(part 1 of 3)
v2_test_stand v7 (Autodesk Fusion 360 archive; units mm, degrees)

design "v2_test_stand" references "DFR0523", "157mm_top_lid", "2020_extrusion_385", "150mm_glass_base"
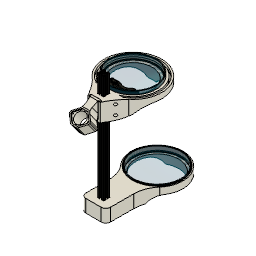
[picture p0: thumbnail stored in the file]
component_insert "Component Insert1"
component_insert "Component Insert2"
component_insert "Component Insert3"
sketch "Sketch1" plane through (0, 321.4508, 0) normal (0, 1, 0) x axis (-1, 0, 0)
  line L1 (-58.2856, 136.7071) -> (0, 97.9412)
  line L2 (0, 167.9412) -> (0, 97.9412)
  line L3 (58.2856, 136.7071) -> (0, 97.9412)
  circle C1 centre (0, 97.9412) radius 70
  circle C2 centre (0, 97.9412) radius 54.7046
  point P3 (0, 97.9412)
  point P4 (0, 97.9412)
  point P5 (-58.2856, 136.7071)
  point P2 (0, 97.9412)
  point P6 (0, 97.9412)
  point P7 (0, 167.9412)
  point P8 (0, 97.9412)
  point P9 (58.2856, 136.7071)
  concentric C1 C2
  coincident P3 P4
  coincident C1 P5
  coincident P2 P6
  vertical L2
  coincident C1 P7
  symmetric P4 L2 P8
  symmetric P5 L2 P9
extrude "Extrude1" new body sketch "Sketch1" profile of C1 C2 L1 L3 along normal blind 10
chamfer "Chamfer1" distance 10 distance 10
fillet "Fillet1" radius 2
sketch "Sketch2" plane through (0, 331.4508, 0) normal (0, 1, 0) x axis (-1, 0, 0)
position "Position1"
position "Position2"
sketch "Sketch3" plane through (0, 331.4508, 0) normal (0, 1, 0) x axis (-1, 0, 0)
  line L1 (58.2856, 136.7071) -> (54.5219, 134.2038)
  line L2 (-54.5219, 134.2038) -> (-58.2856, 136.7071)
  line L3 (-39.9313, 135.9208) -> (-53.1101, 133.8924)
  line L4 (53.1101, 133.8924) -> (39.9313, 135.9208)
  line L5 (0, 167.9412) -> (0, 152.6458)
  line L6 (-12.3083, 151.2431) -> (-14.4131, 166.4413)
  line L7 (12.3083, 151.2431) -> (14.4131, 166.4413)
  arc A1 centre (53.4143, 135.8691) radius 2 clockwise from (54.5219, 134.2038) to (53.1101, 133.8924)
  arc A2 centre (0, 97.9412) radius 70 clockwise from (-58.2856, 136.7071) to (58.2856, 136.7071)
  arc A3 centre (-53.4143, 135.8691) radius 2 clockwise from (-53.1101, 133.8924) to (-54.5219, 134.2038)
  arc A4 centre (-40.2356, 137.8975) radius 2 clockwise from (-38.8165, 136.4882) to (-39.9313, 135.9208)
  arc A5 centre (0, 97.9412) radius 54.7046 clockwise from (-38.8165, 136.4882) to (38.8165, 136.4882)
  arc A6 centre (40.2356, 137.8975) radius 2 clockwise from (39.9313, 135.9208) to (38.8165, 136.4882)
  point P17 (0, 152.6458)
  point P18 (0, 167.9412)
  point P19 (-14.4131, 166.4413)
  point P20 (-12.3083, 151.2431)
  point P21 (14.4131, 166.4413)
  point P22 (12.3083, 151.2431)
  midpoint A5 P17
  midpoint A2 P18
  coincident A2 P19
  coincident A5 P20
  symmetric L5 P19 P21
  symmetric L5 P20 P22
extrude "Extrude2" add sketch "Sketch3" profile of A2 A5 L5 L6 L7 along normal blind 12
fillet "Fillet2" radius 20
sketch "Sketch1" plane through (-21.1609, 0, 137.4854) normal (0.1521, 0, -0.9884) x axis (-0.9884, 0, -0.1521)
  line L1 (-0.9447, 331.4508) -> (-1.1938, 331.4508)
  line L2 (9.0966, 331.4508) -> (-0.9447, 331.4508)
  line L3 (10.2848, 331.4508) -> (9.0966, 331.4508)
  line L4 (23.6187, 331.4508) -> (10.2848, 331.4508)
  line L5 (24.9668, 331.4508) -> (23.6187, 331.4508)
  line L6 (28.3058, 331.4508) -> (24.9668, 331.4508)
  line L7 (-1.1938, 331.4508) -> (28.3058, 331.4508)
sketch "Sketch3" plane through (0, 331.4508, 0) normal (0, 1, 0) x axis (-1, 0, 0)
  curve K1 (21.1809, 143.8255) -> (3.7029, 151.2431)
  curve K2 (5.8078, 166.4413) -> (23.4449, 160.1729)
  line L1 (3.7029, 151.2431) -> (5.8078, 166.4413)
  line L2 (-20.9136, 151.2431) -> (-23.0185, 166.4413)
  line L3 (5.8078, 166.4413) -> (3.7029, 151.2431)
  curve K3 (-40.6556, 160.1729) -> (-23.0185, 166.4413)
  line L4 (-38.3916, 143.8255) -> (-40.6556, 160.1729)
  curve K4 (-20.9136, 151.2431) -> (-38.3916, 143.8255)
  line L5 (-23.0185, 166.4413) -> (-20.9136, 151.2431)
  line L6 (-40.6556, 160.1729) -> (-38.3916, 143.8255)
  line L7 (-63.1272, 134.2038) -> (-66.8909, 136.7071)
  line L8 (-48.5367, 135.9208) -> (-61.7154, 133.8924)
  line L9 (-8.6053, 167.9412) -> (-8.6053, 152.6458)
  line L10 (31.326, 135.9208) -> (44.5047, 133.8924)
  line L11 (49.6802, 136.7071) -> (45.9166, 134.2038)
  curve K5 (23.4449, 160.1729) -> (5.8078, 166.4413)
  arc A1 centre (-8.6053, 97.9412) radius 54.7046 clockwise from (-20.9136, 151.2431) to (3.7029, 151.2431)
  arc A2 centre (-8.6053, 97.9412) radius 70 clockwise from (-23.0185, 166.4413) to (5.8078, 166.4413)
  arc A3 centre (-8.6053, 97.9412) radius 70 clockwise from (-66.8909, 136.7071) to (-40.6556, 160.1729)
  arc A4 centre (-62.0197, 135.8691) radius 2 clockwise from (-61.7154, 133.8924) to (-63.1272, 134.2038)
  arc A5 centre (-48.8409, 137.8975) radius 2 clockwise from (-47.4218, 136.4882) to (-48.5367, 135.9208)
  arc A6 centre (-8.6053, 97.9412) radius 54.7046 clockwise from (-47.4218, 136.4882) to (-38.3916, 143.8255)
  arc A7 centre (-8.6053, 97.9412) radius 54.7046 clockwise from (21.1809, 143.8255) to (30.2111, 136.4882)
  arc A8 centre (31.6302, 137.8975) radius 2 clockwise from (31.326, 135.9208) to (30.2111, 136.4882)
  arc A9 centre (44.809, 135.8691) radius 2 clockwise from (45.9166, 134.2038) to (44.5047, 133.8924)
  arc A10 centre (-8.6053, 97.9412) radius 70 clockwise from (23.4449, 160.1729) to (49.6802, 136.7071)
  point P25 (-8.6053, 152.6458)
  point P26 (-8.6053, 167.9412)
  midpoint A1 P25
  midpoint A2 P26
work_plane "WorkPlane1" AlongDistance 0
sketch "Sketch4" plane through (0, 343.4508, 0) normal (0, 1, 0) x axis (-1, 0, 0)
  line L1 (-20.9136, 151.2431) -> (-23.0185, 166.4413)
  line L2 (5.8078, 166.4413) -> (3.7029, 151.2431)
  curve K1 (21.1809, 143.8255) -> (3.7029, 151.2431)
  line L3 (23.4449, 160.1729) -> (21.1809, 143.8255)
  curve K2 (5.8078, 166.4413) -> (23.4449, 160.1729)
  line L4 (3.7029, 151.2431) -> (5.8078, 166.4413)
  line L5 (21.1809, 143.8255) -> (23.4449, 160.1729)
  line L6 (44.5047, 133.8924) -> (31.326, 135.9208)
  line L7 (49.6802, 136.7071) -> (45.9166, 134.2038)
  line L8 (-8.6053, 167.9412) -> (-8.6053, 152.6458)
  line L9 (45.3089, 103.8063) -> (40.8089, 103.8063)
  line L10 (45.3089, 96.3993) -> (45.3089, 103.8063)
  line L11 (40.8089, 96.3993) -> (45.3089, 96.3993)
  line L12 (40.8089, 103.8063) -> (40.8089, 96.3993)
  line L13 (45.3089, 96.3993) -> (40.8089, 103.8063)
  line L14 (40.8089, 96.3993) -> (45.3089, 103.8063)
  curve K3 (4.9489, 162.359) -> (21.5349, 156.4642)
  curve K4 (25.1345, 149.9158) -> (5.3365, 158.318)
  arc A1 centre (-8.6053, 97.9412) radius 54.7046 clockwise from (-20.9136, 151.2431) to (3.7029, 151.2431)
  arc A2 centre (-8.6053, 97.9412) radius 70 clockwise from (-23.0185, 166.4413) to (5.8078, 166.4413)
  arc A3 centre (-8.6053, 97.9412) radius 54.7046 clockwise from (21.1809, 143.8255) to (30.2111, 136.4882)
  arc A4 centre (31.6302, 137.8975) radius 2 clockwise from (31.326, 135.9208) to (30.2111, 136.4882)
  arc A5 centre (44.809, 135.8691) radius 2 clockwise from (45.9166, 134.2038) to (44.5047, 133.8924)
  arc A6 centre (-8.6053, 97.9412) radius 70 clockwise from (23.4449, 160.1729) to (49.6802, 136.7071)
  arc A7 centre (43.0589, 97.8248) radius 2.6636 clockwise from (45.3089, 96.3993) to (40.8089, 96.3993)
  arc A8 centre (-8.6053, 97.9412) radius 65.8284 clockwise from (21.5349, 156.4642) to (46.2067, 134.3968)
  arc A9 centre (-8.6053, 97.9412) radius 65.8284 clockwise from (-22.1595, 162.359) to (4.9489, 162.359)
  arc A10 centre (-8.6053, 97.9412) radius 61.9656 clockwise from (25.1345, 149.9158) to (35.3633, 141.6046)
  arc A11 centre (-8.6053, 97.9412) radius 61.9656 clockwise from (-22.5473, 158.318) to (5.3365, 158.318)
  arc A12 centre (-11.8522, 103.1847) radius 60.872 clockwise from (35.3633, 141.6046) to (40.3255, 134.5357)
  point P21 (-8.6053, 152.6458)
  point P22 (-8.6053, 167.9412)
  point P27 (43.0589, 100.1028)
  point P41 (40.3255, 134.5357)
  midpoint A1 P21
  midpoint A2 P22
  horizontal L9
  perpendicular L9 L10
  parallel L9 L11
  parallel L10 L12
  coincident L13 P27
  coincident L14 P27
  tangent A3 A12
  coincident L6 P41
  dimension "d13" distance L10 L12 = 4.5
  dimension "d20" = 7.261
sketch "Sketch5" plane through (0, 0, 0) normal (0, 1, 0) x axis (1, 0, 0)
  line L1 (-8.9851, -14.6519) -> (-13.4777, -14.6519)
  line L2 (-8.9851, -23.8412) -> (-8.9851, -14.6519)
  line L3 (-13.4777, -23.8412) -> (-8.9851, -23.8412)
  line L4 (-13.4777, -14.6519) -> (-13.4777, -23.8412)
  line L5 (-8.9851, -23.8412) -> (-13.4777, -14.6519)
  line L6 (-13.4777, -23.8412) -> (-8.9851, -14.6519)
  arc A1 centre (-11.2314, -23.8412) radius 2.2463 clockwise from (-8.9851, -23.8412) to (-13.4777, -23.8412)
  point P6 (-11.2314, -19.2465)
  horizontal L1
  perpendicular L1 L2
  parallel L1 L3
  parallel L2 L4
  coincident L5 P6
  coincident L6 P6
  tangent L4 A1
emboss "Emboss1" sketch "Sketch4" Depth -7 Horizontal Distance 0 Vertical Distance 0 Rotation Angle 0
sketch "Sketch6" plane through (0, 343.4508, 0) normal (0, 1, 0) x axis (-1, 0, 0)
  line L1 (-20.9136, 151.2431) -> (-23.0185, 166.4413)
  line L2 (4.729, 158.6515) -> (3.7029, 151.2431)
  line L3 (5.2589, 162.4778) -> (4.729, 158.6515)
  line L4 (5.8078, 166.4413) -> (5.2589, 162.4778)
  line L5 (-8.6053, 152.6458) -> (-8.6053, 167.9412)
  line L6 (5.2589, 162.4778) -> (-1.0961, 163.3579)
  line L7 (4.729, 158.6515) -> (-1.626, 159.5316)
  arc A1 centre (-8.6053, 97.9412) radius 54.7046 clockwise from (-20.9136, 151.2431) to (3.7029, 151.2431)
  arc A2 centre (-8.6053, 97.9412) radius 70 clockwise from (-23.0185, 166.4413) to (5.8078, 166.4413)
  arc A3 centre (-0.0493, 167.9412) radius 8.5561 clockwise from (-1.626, 159.5316) to (-8.6053, 167.9412)
  arc A4 centre (2.5633, 168.6935) radius 5.8374 clockwise from (1.0129, 163.0658) to (-3.1943, 167.7317)
  point P9 (-8.6053, 167.9412)
  point P10 (-8.6053, 152.6458)
  point P11 (-1.626, 159.5316)
  point P13 (-1.626, 159.5316)
  point P15 (-3.1943, 167.7317)
  point P14 (1.0129, 163.0658)
  point P19 (-1.626, 159.5316)
  point P6 (4.729, 158.6515)
  point P20 (4.729, 158.6515)
  midpoint A2 P9
  midpoint A1 P10
  tangent L5 A3
  coincident P11 P13
  tangent A3 A4
  coincident A2 P15
  coincident P14 L6
  coincident P13 P19
  coincident P6 P20
extrude "Extrude3" cut sketch "Sketch6" profile of L3 A2 A3 A4 L6 L7 against normal blind 7.876
fillet "Fillet3" radius 1
fillet "Fillet4" radius 4
chamfer "Chamfer2" distance 2.438 distance 6.339
fillet "Fillet5" radius 1
work_plane "WorkPlane1" RotateAngle 90
split "Split1"
mirror "Mirror1" mirrorStitchTolerance 0.1
fillet "Fillet6" radius 3
remove_body "RemoveBody1"
sketch "Sketch4" plane through (0, 343.4508, 0) normal (0, 1, 0) x axis (-1, 0, 0)
  line L1 (-10.9032, 158.9882) -> (-6.9794, 159.5316)
  line L2 (-9.8997, 151.7426) -> (-10.9032, 158.9882)
  line L3 (10.9032, 158.9882) -> (9.8997, 151.7426)
  line L4 (6.9794, 159.5316) -> (10.9032, 158.9882)
  line L5 (6.815, 158.5181) -> (9.7456, 158.1122)
  line L6 (-9.7456, 158.1122) -> (-6.815, 158.5181)
  line L7 (-9.0287, 152.9361) -> (-9.7456, 158.1122)
  line L8 (9.7456, 158.1122) -> (9.0287, 152.9361)
  arc A1 centre (0, 160.1735) radius 3 clockwise from (-2.2212, 162.19) to (2.2212, 162.19)
  arc A2 centre (-8.5561, 167.9412) radius 8.5561 clockwise from (-2.2212, 162.19) to (-6.9794, 159.5316)
  arc A3 centre (0, 97.9412) radius 54.7046 clockwise from (-9.8997, 151.7426) to (9.8997, 151.7426)
  arc A4 centre (8.5561, 167.9412) radius 8.5561 clockwise from (6.9794, 159.5316) to (2.2212, 162.19)
  arc A5 centre (8.5561, 167.9412) radius 9.5826 clockwise from (6.815, 158.5181) to (1.4612, 161.5)
  arc A6 centre (0, 160.1735) radius 1.9735 clockwise from (-1.4612, 161.5) to (1.4612, 161.5)
  arc A7 centre (-8.5561, 167.9412) radius 9.5826 clockwise from (-1.4612, 161.5) to (-6.815, 158.5181)
  arc A8 centre (0, 97.9412) radius 55.7311 clockwise from (-9.0287, 152.9361) to (9.0287, 152.9361)
  dimension "d41" = -1.0265
extrude "Extrude4" cut sketch "Sketch4" profile of L8 L7 A8 A7 L6 A6 A5 L5 against normal blind 1.4
sketch "Sketch5" plane through (0, 319.8908, 0) normal (0, -1, 0) x axis (1, 0, 0)
  line L1 (11.3947, 201.5) -> (11.3947, 195.7)
  line L2 (4.5947, 202.5) -> (10.3947, 202.5)
  line L3 (4.5947, 200.7) -> (4.5947, 202.5)
  line L4 (6.3447, 200.7) -> (4.5947, 200.7)
  line L5 (6.8447, 199.1071) -> (6.8447, 200.2)
  line L6 (4.4911, 196.5464) -> (6.6982, 198.7536)
  line L7 (-1.3482, 196.4) -> (4.1375, 196.4)
  line L8 (-3.9089, 198.7536) -> (-1.7018, 196.5464)
  line L9 (-4.0553, 200.2) -> (-4.0553, 199.1071)
  line L10 (-1.8053, 200.7) -> (-3.5553, 200.7)
  line L11 (-1.8053, 202.5) -> (-1.8053, 200.7)
  line L12 (-7.6053, 202.5) -> (-1.8053, 202.5)
  line L13 (-8.6053, 195.7) -> (-8.6053, 201.5)
  line L14 (-6.8053, 195.7) -> (-8.6053, 195.7)
  line L15 (-6.8053, 197.45) -> (-6.8053, 195.7)
  line L16 (-5.2125, 197.95) -> (-6.3053, 197.95)
  line L17 (-2.6518, 195.5964) -> (-4.8589, 197.8036)
  line L18 (-2.5053, 189.7571) -> (-2.5053, 195.2429)
  line L19 (-4.8589, 187.1964) -> (-2.6518, 189.4036)
  line L20 (-6.3053, 187.05) -> (-5.2125, 187.05)
  line L21 (-6.8053, 189.3) -> (-6.8053, 187.55)
  line L22 (-8.6053, 189.3) -> (-6.8053, 189.3)
  line L23 (-8.6053, 183.5) -> (-8.6053, 189.3)
  line L24 (-1.8053, 182.5) -> (-7.6053, 182.5)
  line L25 (-1.8053, 184.3) -> (-1.8053, 182.5)
  line L26 (-3.5553, 184.3) -> (-1.8053, 184.3)
  line L27 (-4.0553, 185.8929) -> (-4.0553, 184.8)
  line L28 (-1.7018, 188.4536) -> (-3.9089, 186.2464)
  line L29 (4.1375, 188.6) -> (-1.3482, 188.6)
  line L30 (6.6982, 186.2464) -> (4.4911, 188.4536)
  line L31 (6.8447, 184.8) -> (6.8447, 185.8929)
  line L32 (4.5947, 184.3) -> (6.3447, 184.3)
  line L33 (4.5947, 182.5) -> (4.5947, 184.3)
  line L34 (10.3947, 182.5) -> (4.5947, 182.5)
  line L35 (11.3947, 189.3) -> (11.3947, 183.5)
  line L36 (9.5947, 189.3) -> (11.3947, 189.3)
  line L37 (9.5947, 187.55) -> (9.5947, 189.3)
  line L38 (8.0018, 187.05) -> (9.0947, 187.05)
  line L39 (5.4411, 189.4036) -> (7.6482, 187.1964)
  line L40 (5.2947, 195.2429) -> (5.2947, 189.7571)
  line L41 (7.6482, 197.8036) -> (5.4411, 195.5964)
  line L42 (9.0947, 197.95) -> (8.0018, 197.95)
  line L43 (9.5947, 195.7) -> (9.5947, 197.45)
  line L44 (11.3947, 195.7) -> (9.5947, 195.7)
  line L45 (21.0401, 215.2474) -> (-18.2508, 215.2474)
  line L46 (21.0401, 169.7526) -> (21.0401, 215.2474)
  line L47 (-18.2508, 169.7526) -> (21.0401, 169.7526)
  line L48 (-18.2508, 215.2474) -> (-18.2508, 169.7526)
  line L49 (21.0401, 169.7526) -> (-18.2508, 215.2474)
  line L50 (-18.2508, 169.7526) -> (21.0401, 215.2474)
  arc A1 centre (10.3947, 201.5) radius 1 clockwise from (10.3947, 202.5) to (11.3947, 201.5)
  arc A2 centre (6.3447, 200.2) radius 0.5 clockwise from (6.3447, 200.7) to (6.8447, 200.2)
  arc A3 centre (6.3447, 199.1071) radius 0.5 clockwise from (6.8447, 199.1071) to (6.6982, 198.7536)
  arc A4 centre (4.1375, 196.9) radius 0.5 clockwise from (4.4911, 196.5464) to (4.1375, 196.4)
  arc A5 centre (-1.3482, 196.9) radius 0.5 clockwise from (-1.3482, 196.4) to (-1.7018, 196.5464)
  arc A6 centre (-3.5553, 199.1071) radius 0.5 clockwise from (-3.9089, 198.7536) to (-4.0553, 199.1071)
  arc A7 centre (-3.5553, 200.2) radius 0.5 clockwise from (-4.0553, 200.2) to (-3.5553, 200.7)
  arc A8 centre (-7.6053, 201.5) radius 1 clockwise from (-8.6053, 201.5) to (-7.6053, 202.5)
  arc A9 centre (-6.3053, 197.45) radius 0.5 clockwise from (-6.8053, 197.45) to (-6.3053, 197.95)
  arc A10 centre (-5.2125, 197.45) radius 0.5 clockwise from (-5.2125, 197.95) to (-4.8589, 197.8036)
  arc A11 centre (-3.0053, 195.2429) radius 0.5 clockwise from (-2.6518, 195.5964) to (-2.5053, 195.2429)
  arc A12 centre (-3.0053, 189.7571) radius 0.5 clockwise from (-2.5053, 189.7571) to (-2.6518, 189.4036)
  arc A13 centre (-5.2125, 187.55) radius 0.5 clockwise from (-4.8589, 187.1964) to (-5.2125, 187.05)
  arc A14 centre (-6.3053, 187.55) radius 0.5 clockwise from (-6.3053, 187.05) to (-6.8053, 187.55)
  arc A15 centre (-7.6053, 183.5) radius 1 clockwise from (-7.6053, 182.5) to (-8.6053, 183.5)
  arc A16 centre (-3.5553, 184.8) radius 0.5 clockwise from (-3.5553, 184.3) to (-4.0553, 184.8)
  arc A17 centre (-3.5553, 185.8929) radius 0.5 clockwise from (-4.0553, 185.8929) to (-3.9089, 186.2464)
  arc A18 centre (-1.3482, 188.1) radius 0.5 clockwise from (-1.7018, 188.4536) to (-1.3482, 188.6)
  arc A19 centre (4.1375, 188.1) radius 0.5 clockwise from (4.1375, 188.6) to (4.4911, 188.4536)
  arc A20 centre (6.3447, 185.8929) radius 0.5 clockwise from (6.6982, 186.2464) to (6.8447, 185.8929)
  arc A21 centre (6.3447, 184.8) radius 0.5 clockwise from (6.8447, 184.8) to (6.3447, 184.3)
  arc A22 centre (10.3947, 183.5) radius 1 clockwise from (11.3947, 183.5) to (10.3947, 182.5)
  arc A23 centre (9.0947, 187.55) radius 0.5 clockwise from (9.5947, 187.55) to (9.0947, 187.05)
  arc A24 centre (8.0018, 187.55) radius 0.5 clockwise from (8.0018, 187.05) to (7.6482, 187.1964)
  arc A25 centre (5.7947, 189.7571) radius 0.5 clockwise from (5.4411, 189.4036) to (5.2947, 189.7571)
  arc A26 centre (5.7947, 195.2429) radius 0.5 clockwise from (5.2947, 195.2429) to (5.4411, 195.5964)
  arc A27 centre (8.0018, 197.45) radius 0.5 clockwise from (7.6482, 197.8036) to (8.0018, 197.95)
  arc A28 centre (9.0947, 197.45) radius 0.5 clockwise from (9.0947, 197.95) to (9.5947, 197.45)
  circle C1 centre (1.3947, 192.5) radius 2.5
  circle C2 centre (0, 97.9412) radius 72.5
  circle C3 centre (0, 97.9412) radius 72.7
  circle C4 centre (0, 97.9412) radius 92.5
  point P110 (1.3947, 192.5)
  point P102 (1.3947, 192.5)
  horizontal L45
  perpendicular L45 L46
  parallel L45 L47
  parallel L46 L48
  coincident L49 P110
  coincident L50 P110
  coincident P102 P110
  dimension "d44" = 0.2
  dimension "d45" = 20
extrude "Extrude5" new body sketch "Sketch5" profile of L1 A1 L2 L3 L4 A2 L5 A3 L6 A4 L7 A5 L8 A6 L9 A7 L10 L11 L12 A8 L13 L14 L15 A9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 along normal blind 10
sketch "Sketch6" plane through (0, 319.8908, 0) normal (0, 1, 0) x axis (-1, 0, 0)
  line L1 (-9.5947, 195.7) -> (-9.5947, 197.45)
  line L2 (-11.3947, 195.7) -> (-9.5947, 195.7)
  line L3 (-11.3947, 201.5) -> (-11.3947, 195.7)
  line L4 (-4.5947, 202.5) -> (-10.3947, 202.5)
  line L5 (-4.5947, 200.7) -> (-4.5947, 202.5)
  line L6 (-6.3447, 200.7) -> (-4.5947, 200.7)
  line L7 (-6.8447, 199.1071) -> (-6.8447, 200.2)
  line L8 (-4.4911, 196.5464) -> (-6.6982, 198.7536)
  line L9 (1.3482, 196.4) -> (-4.1375, 196.4)
  line L10 (3.9089, 198.7536) -> (1.7018, 196.5464)
  line L11 (4.0553, 200.2) -> (4.0553, 199.1071)
  line L12 (1.8053, 200.7) -> (3.5553, 200.7)
  line L13 (1.8053, 202.5) -> (1.8053, 200.7)
  line L14 (7.6053, 202.5) -> (1.8053, 202.5)
  line L15 (8.6053, 195.7) -> (8.6053, 201.5)
  line L16 (6.8053, 195.7) -> (8.6053, 195.7)
  line L17 (6.8053, 197.45) -> (6.8053, 195.7)
  line L18 (5.2125, 197.95) -> (6.3053, 197.95)
  line L19 (2.6518, 195.5964) -> (4.8589, 197.8036)
  line L20 (2.5053, 189.7571) -> (2.5053, 195.2429)
  line L21 (4.8589, 187.1964) -> (2.6518, 189.4036)
  line L22 (6.3053, 187.05) -> (5.2125, 187.05)
  line L23 (6.8053, 189.3) -> (6.8053, 187.55)
  line L24 (8.6053, 189.3) -> (6.8053, 189.3)
  line L25 (8.6053, 183.5) -> (8.6053, 189.3)
  line L26 (1.8053, 182.5) -> (7.6053, 182.5)
  line L27 (1.8053, 184.3) -> (1.8053, 182.5)
  line L28 (3.5553, 184.3) -> (1.8053, 184.3)
  line L29 (4.0553, 185.8929) -> (4.0553, 184.8)
  line L30 (1.7018, 188.4536) -> (3.9089, 186.2464)
  line L31 (-4.1375, 188.6) -> (1.3482, 188.6)
  line L32 (-6.6982, 186.2464) -> (-4.4911, 188.4536)
  line L33 (-6.8447, 184.8) -> (-6.8447, 185.8929)
  line L34 (-4.5947, 184.3) -> (-6.3447, 184.3)
  line L35 (-4.5947, 182.5) -> (-4.5947, 184.3)
  line L36 (-10.3947, 182.5) -> (-4.5947, 182.5)
  line L37 (-11.3947, 189.3) -> (-11.3947, 183.5)
  line L38 (-9.5947, 189.3) -> (-11.3947, 189.3)
  line L39 (-9.5947, 187.55) -> (-9.5947, 189.3)
  line L40 (-8.0018, 187.05) -> (-9.0947, 187.05)
  line L41 (-5.4411, 189.4036) -> (-7.6482, 187.1964)
  line L42 (-5.2947, 195.2429) -> (-5.2947, 189.7571)
  line L43 (-7.6482, 197.8036) -> (-5.4411, 195.5964)
  line L44 (-9.0947, 197.95) -> (-8.0018, 197.95)
  line L45 (18.2508, 215.2474) -> (18.2508, 188.6228)
  line L46 (-21.0401, 215.2474) -> (18.2508, 215.2474)
  line L47 (-21.0401, 188.0165) -> (-21.0401, 215.2474)
  circle C1 centre (0, 97.9412) radius 74.5
  circle C2 centre (0, 97.9412) radius 74.7
  arc A1 centre (-10.3947, 201.5) radius 1 clockwise from (-11.3947, 201.5) to (-10.3947, 202.5)
  arc A2 centre (-6.3447, 200.2) radius 0.5 clockwise from (-6.8447, 200.2) to (-6.3447, 200.7)
  arc A3 centre (-6.3447, 199.1071) radius 0.5 clockwise from (-6.6982, 198.7536) to (-6.8447, 199.1071)
  arc A4 centre (-4.1375, 196.9) radius 0.5 clockwise from (-4.1375, 196.4) to (-4.4911, 196.5464)
  arc A5 centre (1.3482, 196.9) radius 0.5 clockwise from (1.7018, 196.5464) to (1.3482, 196.4)
  arc A6 centre (3.5553, 199.1071) radius 0.5 clockwise from (4.0553, 199.1071) to (3.9089, 198.7536)
  arc A7 centre (3.5553, 200.2) radius 0.5 clockwise from (3.5553, 200.7) to (4.0553, 200.2)
  arc A8 centre (7.6053, 201.5) radius 1 clockwise from (7.6053, 202.5) to (8.6053, 201.5)
  arc A9 centre (6.3053, 197.45) radius 0.5 clockwise from (6.3053, 197.95) to (6.8053, 197.45)
  arc A10 centre (5.2125, 197.45) radius 0.5 clockwise from (4.8589, 197.8036) to (5.2125, 197.95)
  arc A11 centre (3.0053, 195.2429) radius 0.5 clockwise from (2.5053, 195.2429) to (2.6518, 195.5964)
  arc A12 centre (3.0053, 189.7571) radius 0.5 clockwise from (2.6518, 189.4036) to (2.5053, 189.7571)
  arc A13 centre (5.2125, 187.55) radius 0.5 clockwise from (5.2125, 187.05) to (4.8589, 187.1964)
  arc A14 centre (6.3053, 187.55) radius 0.5 clockwise from (6.8053, 187.55) to (6.3053, 187.05)
  arc A15 centre (7.6053, 183.5) radius 1 clockwise from (8.6053, 183.5) to (7.6053, 182.5)
  arc A16 centre (3.5553, 184.8) radius 0.5 clockwise from (4.0553, 184.8) to (3.5553, 184.3)
  arc A17 centre (3.5553, 185.8929) radius 0.5 clockwise from (3.9089, 186.2464) to (4.0553, 185.8929)
  arc A18 centre (1.3482, 188.1) radius 0.5 clockwise from (1.3482, 188.6) to (1.7018, 188.4536)
  arc A19 centre (-4.1375, 188.1) radius 0.5 clockwise from (-4.4911, 188.4536) to (-4.1375, 188.6)
  arc A20 centre (-6.3447, 185.8929) radius 0.5 clockwise from (-6.8447, 185.8929) to (-6.6982, 186.2464)
  arc A21 centre (-6.3447, 184.8) radius 0.5 clockwise from (-6.3447, 184.3) to (-6.8447, 184.8)
  arc A22 centre (-10.3947, 183.5) radius 1 clockwise from (-10.3947, 182.5) to (-11.3947, 183.5)
  arc A23 centre (-9.0947, 187.55) radius 0.5 clockwise from (-9.0947, 187.05) to (-9.5947, 187.55)
  arc A24 centre (-8.0018, 187.55) radius 0.5 clockwise from (-7.6482, 187.1964) to (-8.0018, 187.05)
  arc A25 centre (-5.7947, 189.7571) radius 0.5 clockwise from (-5.2947, 189.7571) to (-5.4411, 189.4036)
  arc A26 centre (-5.7947, 195.2429) radius 0.5 clockwise from (-5.4411, 195.5964) to (-5.2947, 195.2429)
  arc A27 centre (-8.0018, 197.45) radius 0.5 clockwise from (-8.0018, 197.95) to (-7.6482, 197.8036)
  arc A28 centre (-9.0947, 197.45) radius 0.5 clockwise from (-9.5947, 197.45) to (-9.0947, 197.95)
  arc A29 centre (0, 97.9412) radius 92.5 clockwise from (18.2508, 188.6228) to (-21.0401, 188.0165)
  dimension "d48" = 0.2
extrude "Extrude6" add sketch "Sketch6" profile of C2 L1 L2 L3 A1 L4 L5 L6 A2 L7 A3 L8 A4 L9 A5 L10 A6 L11 A7 L12 L13 L14 A8 L15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 along normal blind 7.53
chamfer "Chamfer3" distance 42 distance 10 distance 10 distance 42
sketch "Sketch7" plane through (0, 309.8908, 0) normal (0, -1, 0) x axis (1, 0, 0)
  circle C1 centre (0, 97.9412) radius 70
  circle C2 centre (0, 97.9412) radius 62
  concentric C1 C2
  dimension "d55" distance C1 C2 = 8
extrude "Extrude7" cut sketch "Sketch7" profile of C2 against normal blind 11.56
sketch "Sketch8" plane through (0, 309.8908, 0) normal (0, -1, 0) x axis (1, 0, 0)
  line L1 (9.5947, 197.45) -> (9.5947, 195.7)
  line L2 (8.0018, 197.95) -> (9.0947, 197.95)
  line L3 (5.4411, 195.5964) -> (7.6482, 197.8036)
  line L4 (5.2947, 189.7571) -> (5.2947, 195.2429)
  line L5 (7.6482, 187.1964) -> (5.4411, 189.4036)
  line L6 (9.0947, 187.05) -> (8.0018, 187.05)
  line L7 (9.5947, 189.3) -> (9.5947, 187.55)
  line L8 (11.3947, 189.3) -> (9.5947, 189.3)
  line L9 (11.3947, 183.5) -> (11.3947, 189.3)
  line L10 (4.5947, 182.5) -> (10.3947, 182.5)
  line L11 (4.5947, 184.3) -> (4.5947, 182.5)
  line L12 (6.3447, 184.3) -> (4.5947, 184.3)
  line L13 (6.8447, 185.8929) -> (6.8447, 184.8)
  line L14 (4.4911, 188.4536) -> (6.6982, 186.2464)
  line L15 (-1.3482, 188.6) -> (4.1375, 188.6)
  line L16 (-3.9089, 186.2464) -> (-1.7018, 188.4536)
  line L17 (-4.0553, 184.8) -> (-4.0553, 185.8929)
  line L18 (-1.8053, 184.3) -> (-3.5553, 184.3)
  line L19 (-1.8053, 182.5) -> (-1.8053, 184.3)
  line L20 (-7.6053, 182.5) -> (-1.8053, 182.5)
  line L21 (-8.6053, 189.3) -> (-8.6053, 183.5)
  line L22 (-6.8053, 189.3) -> (-8.6053, 189.3)
  line L23 (-6.8053, 187.55) -> (-6.8053, 189.3)
  line L24 (-5.2125, 187.05) -> (-6.3053, 187.05)
  line L25 (-2.6518, 189.4036) -> (-4.8589, 187.1964)
  line L26 (-2.5053, 195.2429) -> (-2.5053, 189.7571)
  line L27 (-4.8589, 197.8036) -> (-2.6518, 195.5964)
  line L28 (-6.3053, 197.95) -> (-5.2125, 197.95)
  line L29 (-6.8053, 195.7) -> (-6.8053, 197.45)
  line L30 (-8.6053, 195.7) -> (-6.8053, 195.7)
  line L31 (-8.6053, 201.5) -> (-8.6053, 195.7)
  line L32 (-1.8053, 202.5) -> (-7.6053, 202.5)
  line L33 (-1.8053, 200.7) -> (-1.8053, 202.5)
  line L34 (-3.5553, 200.7) -> (-1.8053, 200.7)
  line L35 (-4.0553, 199.1071) -> (-4.0553, 200.2)
  line L36 (-1.7018, 196.5464) -> (-3.9089, 198.7536)
  line L37 (4.1375, 196.4) -> (-1.3482, 196.4)
  line L38 (6.6982, 198.7536) -> (4.4911, 196.5464)
  line L39 (6.8447, 200.2) -> (6.8447, 199.1071)
  line L40 (4.5947, 200.7) -> (6.3447, 200.7)
  line L41 (4.5947, 202.5) -> (4.5947, 200.7)
  line L42 (10.3947, 202.5) -> (4.5947, 202.5)
  line L43 (11.3947, 195.7) -> (11.3947, 201.5)
  line L44 (9.5947, 195.7) -> (11.3947, 195.7)
  line L45 (-18.2508, 198.6228) -> (-18.2508, 215.2474)
  line L46 (-56.4687, 171.2046) -> (-18.2508, 198.6228)
  line L47 (21.0401, 198.0165) -> (58.7024, 169.4274)
  line L48 (21.0401, 215.2474) -> (21.0401, 198.0165)
  line L49 (-18.2508, 215.2474) -> (21.0401, 215.2474)
  line L50 (0, 5.4412) -> (0, 97.9412)
  line L51 (18.6886, 7.3488) -> (0, 97.9412)
  line L52 (-18.6886, 7.3488) -> (0, 97.9412)
  circle C1 centre (0, 97.9412) radius 62
  arc A1 centre (9.0947, 197.45) radius 0.5 clockwise from (9.0947, 197.95) to (9.5947, 197.45)
  arc A2 centre (8.0018, 197.45) radius 0.5 clockwise from (7.6482, 197.8036) to (8.0018, 197.95)
  arc A3 centre (5.7947, 195.2429) radius 0.5 clockwise from (5.2947, 195.2429) to (5.4411, 195.5964)
  arc A4 centre (5.7947, 189.7571) radius 0.5 clockwise from (5.4411, 189.4036) to (5.2947, 189.7571)
  arc A5 centre (8.0018, 187.55) radius 0.5 clockwise from (8.0018, 187.05) to (7.6482, 187.1964)
  arc A6 centre (9.0947, 187.55) radius 0.5 clockwise from (9.5947, 187.55) to (9.0947, 187.05)
  arc A7 centre (10.3947, 183.5) radius 1 clockwise from (11.3947, 183.5) to (10.3947, 182.5)
  arc A8 centre (6.3447, 184.8) radius 0.5 clockwise from (6.8447, 184.8) to (6.3447, 184.3)
  arc A9 centre (6.3447, 185.8929) radius 0.5 clockwise from (6.6982, 186.2464) to (6.8447, 185.8929)
  arc A10 centre (4.1375, 188.1) radius 0.5 clockwise from (4.1375, 188.6) to (4.4911, 188.4536)
  arc A11 centre (-1.3482, 188.1) radius 0.5 clockwise from (-1.7018, 188.4536) to (-1.3482, 188.6)
  arc A12 centre (-3.5553, 185.8929) radius 0.5 clockwise from (-4.0553, 185.8929) to (-3.9089, 186.2464)
  arc A13 centre (-3.5553, 184.8) radius 0.5 clockwise from (-3.5553, 184.3) to (-4.0553, 184.8)
  arc A14 centre (-7.6053, 183.5) radius 1 clockwise from (-7.6053, 182.5) to (-8.6053, 183.5)
  arc A15 centre (-6.3053, 187.55) radius 0.5 clockwise from (-6.3053, 187.05) to (-6.8053, 187.55)
  arc A16 centre (-5.2125, 187.55) radius 0.5 clockwise from (-4.8589, 187.1964) to (-5.2125, 187.05)
  arc A17 centre (-3.0053, 189.7571) radius 0.5 clockwise from (-2.5053, 189.7571) to (-2.6518, 189.4036)
  arc A18 centre (-3.0053, 195.2429) radius 0.5 clockwise from (-2.6518, 195.5964) to (-2.5053, 195.2429)
  arc A19 centre (-5.2125, 197.45) radius 0.5 clockwise from (-5.2125, 197.95) to (-4.8589, 197.8036)
  arc A20 centre (-6.3053, 197.45) radius 0.5 clockwise from (-6.8053, 197.45) to (-6.3053, 197.95)
  arc A21 centre (-7.6053, 201.5) radius 1 clockwise from (-8.6053, 201.5) to (-7.6053, 202.5)
  arc A22 centre (-3.5553, 200.2) radius 0.5 clockwise from (-4.0553, 200.2) to (-3.5553, 200.7)
  arc A23 centre (-3.5553, 199.1071) radius 0.5 clockwise from (-3.9089, 198.7536) to (-4.0553, 199.1071)
  arc A24 centre (-1.3482, 196.9) radius 0.5 clockwise from (-1.3482, 196.4) to (-1.7018, 196.5464)
  arc A25 centre (4.1375, 196.9) radius 0.5 clockwise from (4.4911, 196.5464) to (4.1375, 196.4)
  arc A26 centre (6.3447, 199.1071) radius 0.5 clockwise from (6.8447, 199.1071) to (6.6982, 198.7536)
  arc A27 centre (6.3447, 200.2) radius 0.5 clockwise from (6.3447, 200.7) to (6.8447, 200.2)
  arc A28 centre (10.3947, 201.5) radius 1 clockwise from (10.3947, 202.5) to (11.3947, 201.5)
  arc A29 centre (0, 97.9412) radius 92.5 clockwise from (58.7024, 169.4274) to (-56.4687, 171.2046)
  point P2 (0, 97.9412)
  point P109 (0, 97.9412)
  point P110 (0, 5.4412)
  point P111 (18.6886, 7.3488)
  point P112 (0, 97.9412)
  point P113 (-18.6886, 7.3488)
  coincident P2 P109
  coincident A29 P110
  vertical L50
  coincident A29 P111
  symmetric P109 L50 P112
  symmetric L50 P111 P113
extrude "Extrude8" add sketch "Sketch8" profile of C1 A29 L50 L51 L52 along normal blind 24
fillet "Fillet7" radius 70.291
sketch "Sketch9" plane through (0, 309.8908, 0) normal (0, -1, 0) x axis (1, 0, 0)
  line L1 (-58.3394, 76.9527) -> (-67.1363, 34.3097)
  line L2 (67.1364, 34.3097) -> (58.3394, 76.9527)
  line L3 (21.0401, 198.0165) -> (58.7024, 169.4274)
  line L4 (21.0401, 215.2474) -> (21.0401, 198.0165)
  line L5 (-18.2508, 215.2474) -> (21.0401, 215.2474)
  line L6 (-18.2508, 198.6228) -> (-18.2508, 215.2474)
  line L7 (-56.4687, 171.2046) -> (-18.2508, 198.6228)
  line L8 (9.5947, 197.45) -> (9.5947, 195.7)
  line L9 (8.0018, 197.95) -> (9.0947, 197.95)
  line L10 (5.4411, 195.5964) -> (7.6482, 197.8036)
  line L11 (5.2947, 189.7571) -> (5.2947, 195.2429)
  line L12 (7.6482, 187.1964) -> (5.4411, 189.4036)
  line L13 (9.0947, 187.05) -> (8.0018, 187.05)
  line L14 (9.5947, 189.3) -> (9.5947, 187.55)
  line L15 (11.3947, 189.3) -> (9.5947, 189.3)
  line L16 (11.3947, 183.5) -> (11.3947, 189.3)
  line L17 (4.5947, 182.5) -> (10.3947, 182.5)
  line L18 (4.5947, 184.3) -> (4.5947, 182.5)
  line L19 (6.3447, 184.3) -> (4.5947, 184.3)
  line L20 (6.8447, 185.8929) -> (6.8447, 184.8)
  line L21 (4.4911, 188.4536) -> (6.6982, 186.2464)
  line L22 (-1.3482, 188.6) -> (4.1375, 188.6)
  line L23 (-3.9089, 186.2464) -> (-1.7018, 188.4536)
  line L24 (-4.0553, 184.8) -> (-4.0553, 185.8929)
  line L25 (-1.8053, 184.3) -> (-3.5553, 184.3)
  line L26 (-1.8053, 182.5) -> (-1.8053, 184.3)
  line L27 (-7.6053, 182.5) -> (-1.8053, 182.5)
  line L28 (-8.6053, 189.3) -> (-8.6053, 183.5)
  line L29 (-6.8053, 189.3) -> (-8.6053, 189.3)
  line L30 (-6.8053, 187.55) -> (-6.8053, 189.3)
  line L31 (-5.2125, 187.05) -> (-6.3053, 187.05)
  line L32 (-2.6518, 189.4036) -> (-4.8589, 187.1964)
  line L33 (-2.5053, 195.2429) -> (-2.5053, 189.7571)
  line L34 (-4.8589, 197.8036) -> (-2.6518, 195.5964)
  line L35 (-6.3053, 197.95) -> (-5.2125, 197.95)
  line L36 (-6.8053, 195.7) -> (-6.8053, 197.45)
  line L37 (-8.6053, 195.7) -> (-6.8053, 195.7)
  line L38 (-8.6053, 201.5) -> (-8.6053, 195.7)
  line L39 (-1.8053, 202.5) -> (-7.6053, 202.5)
  line L40 (-1.8053, 200.7) -> (-1.8053, 202.5)
  line L41 (-3.5553, 200.7) -> (-1.8053, 200.7)
  line L42 (-4.0553, 199.1071) -> (-4.0553, 200.2)
  line L43 (-1.7018, 196.5464) -> (-3.9089, 198.7536)
  line L44 (4.1375, 196.4) -> (-1.3482, 196.4)
  line L45 (6.6982, 198.7536) -> (4.4911, 196.5464)
  line L46 (6.8447, 200.2) -> (6.8447, 199.1071)
  line L47 (4.5947, 200.7) -> (6.3447, 200.7)
  line L48 (4.5947, 202.5) -> (4.5947, 200.7)
  line L49 (10.3947, 202.5) -> (4.5947, 202.5)
  line L50 (11.3947, 195.7) -> (11.3947, 201.5)
  line L51 (9.5947, 195.7) -> (11.3947, 195.7)
  line L52 (-56.4687, 171.2046) -> (0, 97.9412)
  line L53 (58.7024, 169.4274) -> (0, 97.9412)
  arc A1 centre (0, 97.9412) radius 62 clockwise from (-58.3394, 76.9527) to (58.3394, 76.9527)
  arc A2 centre (0, 97.9412) radius 92.5 clockwise from (58.7024, 169.4274) to (67.1364, 34.3097)
  arc A3 centre (0, 97.9412) radius 92.5 clockwise from (-67.1363, 34.3097) to (-56.4687, 171.2046)
  arc A4 centre (9.0947, 197.45) radius 0.5 clockwise from (9.0947, 197.95) to (9.5947, 197.45)
  arc A5 centre (8.0018, 197.45) radius 0.5 clockwise from (7.6482, 197.8036) to (8.0018, 197.95)
  arc A6 centre (5.7947, 195.2429) radius 0.5 clockwise from (5.2947, 195.2429) to (5.4411, 195.5964)
  arc A7 centre (5.7947, 189.7571) radius 0.5 clockwise from (5.4411, 189.4036) to (5.2947, 189.7571)
  arc A8 centre (8.0018, 187.55) radius 0.5 clockwise from (8.0018, 187.05) to (7.6482, 187.1964)
  arc A9 centre (9.0947, 187.55) radius 0.5 clockwise from (9.5947, 187.55) to (9.0947, 187.05)
  arc A10 centre (10.3947, 183.5) radius 1 clockwise from (11.3947, 183.5) to (10.3947, 182.5)
  arc A11 centre (6.3447, 184.8) radius 0.5 clockwise from (6.8447, 184.8) to (6.3447, 184.3)
  arc A12 centre (6.3447, 185.8929) radius 0.5 clockwise from (6.6982, 186.2464) to (6.8447, 185.8929)
  arc A13 centre (4.1375, 188.1) radius 0.5 clockwise from (4.1375, 188.6) to (4.4911, 188.4536)
  arc A14 centre (-1.3482, 188.1) radius 0.5 clockwise from (-1.7018, 188.4536) to (-1.3482, 188.6)
  arc A15 centre (-3.5553, 185.8929) radius 0.5 clockwise from (-4.0553, 185.8929) to (-3.9089, 186.2464)
  arc A16 centre (-3.5553, 184.8) radius 0.5 clockwise from (-3.5553, 184.3) to (-4.0553, 184.8)
  arc A17 centre (-7.6053, 183.5) radius 1 clockwise from (-7.6053, 182.5) to (-8.6053, 183.5)
  arc A18 centre (-6.3053, 187.55) radius 0.5 clockwise from (-6.3053, 187.05) to (-6.8053, 187.55)
  arc A19 centre (-5.2125, 187.55) radius 0.5 clockwise from (-4.8589, 187.1964) to (-5.2125, 187.05)
  arc A20 centre (-3.0053, 189.7571) radius 0.5 clockwise from (-2.5053, 189.7571) to (-2.6518, 189.4036)
  arc A21 centre (-3.0053, 195.2429) radius 0.5 clockwise from (-2.6518, 195.5964) to (-2.5053, 195.2429)
  arc A22 centre (-5.2125, 197.45) radius 0.5 clockwise from (-5.2125, 197.95) to (-4.8589, 197.8036)
  arc A23 centre (-6.3053, 197.45) radius 0.5 clockwise from (-6.8053, 197.45) to (-6.3053, 197.95)
  arc A24 centre (-7.6053, 201.5) radius 1 clockwise from (-8.6053, 201.5) to (-7.6053, 202.5)
  arc A25 centre (-3.5553, 200.2) radius 0.5 clockwise from (-4.0553, 200.2) to (-3.5553, 200.7)
  arc A26 centre (-3.5553, 199.1071) radius 0.5 clockwise from (-3.9089, 198.7536) to (-4.0553, 199.1071)
  arc A27 centre (-1.3482, 196.9) radius 0.5 clockwise from (-1.3482, 196.4) to (-1.7018, 196.5464)
  arc A28 centre (4.1375, 196.9) radius 0.5 clockwise from (4.4911, 196.5464) to (4.1375, 196.4)
  arc A29 centre (6.3447, 199.1071) radius 0.5 clockwise from (6.8447, 199.1071) to (6.6982, 198.7536)
  arc A30 centre (6.3447, 200.2) radius 0.5 clockwise from (6.3447, 200.7) to (6.8447, 200.2)
  arc A31 centre (10.3947, 201.5) radius 1 clockwise from (10.3947, 202.5) to (11.3947, 201.5)
  point P5 (0, 97.9412)
  point P113 (0, 97.9412)
  point P12 (-56.4687, 171.2046)
  point P114 (-56.4687, 171.2046)
  point P7 (58.7024, 169.4274)
  point P115 (58.7024, 169.4274)
  coincident P5 P113
  coincident P12 P114
  coincident P7 P115
extrude "Extrude9" add sketch "Sketch9" profile of A1 L3 L4 L5 L6 L7 L8 A4 L9 A5 L10 A6 L11 A7 L12 A8 L13 A9 L14 L15 L16 A10 L17 L18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 along normal blind 40
fillet "Fillet8" radius 69.663 94.526
extrude "Extrude10" add of existing geometry blind 8.164
sketch "Sketch10" plane through (0, 327.4208, 0) normal (0, 1, 0) x axis (-1, 0, 0)
  line L1 (18.6886, 7.3488) -> (12.5264, 37.2198)
  line L2 (-12.5264, 37.2198) -> (-18.6886, 7.3488)
  line L3 (-2.2466, 13.6804) -> (4.7527, 13.7845)
  line L4 (-47.1679, 164.8836) -> (-55.5285, 164.5135)
  line L5 (47.849, 170.2306) -> (50.8224, 162.1532)
  arc A1 centre (0, 97.9412) radius 92.5 clockwise from (18.6886, 7.3488) to (-18.6886, 7.3488)
  arc A2 centre (0, 97.9412) radius 62 clockwise from (12.5264, 37.2198) to (-12.5264, 37.2198)
  arc A3 centre (0, 97.9412) radius 92.5 clockwise from (56.4687, 171.2046) to (-58.7024, 169.4274)
  arc A4 centre (0, 97.9412) radius 81.8908 clockwise from (50.8224, 162.1532) to (-47.1679, 164.8836)
  arc A5 centre (0, 97.9412) radius 86.6908 clockwise from (47.849, 170.2306) to (-55.5285, 164.5135)
  circle C1 centre (4.7527, 13.7845) radius 2.4
  circle C2 centre (-2.2466, 13.6804) radius 2.4
  point P16 (4.7527, 13.7845)
  point P18 (4.7527, 13.7845)
  point P17 (-2.2466, 13.6804)
  point P19 (-2.2466, 13.6804)
  coincident P16 P18
  tangent A5 C1
  coincident P17 P19
  tangent A5 C2
  tangent A4 C1
  tangent A4 C2
  dimension "d74" = -5.8092
  dimension "d75" distance A4 A5 = 4.8
  dimension "d76" distance P16 P17 = 7
extrude "Extrude11" cut sketch "Sketch10" profile of A4 A5 L3 C1 C2 against normal blind 55.929
extrude "Extrude12" cut sketch "Sketch10" profile of L1 L2 A4 A5 C1 C2 L4 L5 against normal blind 8
chamfer "Chamfer5" distance 7.884
ground "Pin"
fillet "Fillet10" radius 217.961
work_plane "WorkPlane2"
work_plane "WorkPlane3" RotateAngle 60
sketch "Sketch11" plane through (-110.4281, 0, 63.7557) normal (-0.866, 0, 0.5) x axis (0, -1, 0)
  line L1 (-269.8908, 165.163) -> (-269.8908, 184.3545)
  line L2 (-327.4208, 184.3545) -> (-269.8908, 184.3545)
  line L3 (-327.4208, 120.0332) -> (-327.4208, 184.3545)
  line L4 (-280.9512, 120.0332) -> (-327.4208, 120.0332)
  curve K1 (-269.8908, 165.163) -> (-280.9512, 120.0332)
  line L5 (-282.4208, 176.1086) -> (-327.4208, 176.1086)
  line L6 (-282.4208, 136.1086) -> (-282.4208, 176.1086)
  line L7 (-327.4208, 136.1086) -> (-282.4208, 136.1086)
  line L8 (-327.4208, 176.1086) -> (-327.4208, 136.1086)
  point P7 (-327.4208, 176.1086)
  point P11 (-327.4208, 176.1086)
  point P8 (-282.4208, 176.1086)
  point P10 (-327.4208, 136.1086)
  horizontal L5
  vertical L6
  horizontal L7
  vertical L8
  coincident P7 P11
  dimension "d85" distance P7 P8 = 45
  dimension "d86" distance P7 P10 = 40
work_plane "WorkPlane4" AlongDistance -64.73
sketch "Sketch12" plane through (-63.3353, 0, 0) normal (1, 0, 0) x axis (0, 0, -1)
  line L1 (-195.2429, 383.2592) -> (-195.2429, -1.7408)
  line L2 (-189.7571, 383.2592) -> (-195.2429, 383.2592)
  line L3 (-189.7571, -1.7408) -> (-189.7571, 383.2592)
  line L4 (-195.2429, -1.7408) -> (-189.7571, -1.7408)
  line L5 (-195.2429, 315.4208) -> (-189.7571, 315.4208)
  line L6 (-195.2429, 285.4208) -> (-189.7571, 285.4208)
  line L7 (-223.4114, 327.4208) -> (-171.2046, 327.4208)
  circle C1 centre (-192.5, 285.4208) radius 4
  circle C2 centre (-192.5, 315.4208) radius 4
  point P6 (-189.7571, 315.4208)
  point P7 (-195.2429, 315.4208)
  point P8 (-189.7571, 285.4208)
  point P9 (-195.2429, 285.4208)
  point P12 (-192.5, 285.4208)
  point P13 (-192.5, 315.4208)
  coincident L3 P6
  coincident L1 P7
  perpendicular L1 L5
  coincident L3 P8
  coincident L1 P9
  perpendicular L1 L6
  midpoint L6 P12
  midpoint L5 P13
  dimension "d88" distance L5 L6 = 30
  dimension "d89" distance L5 L7 = 12
  dimension "d90" diameter C1 = 8
  dimension "d91" diameter C2 = 8
extrude "Extrude13" cut sketch "Sketch12" profile of C1 C2 along normal blind 38
sketch "Sketch13" plane through (-25.3353, 0, 0) normal (-1, 0, 0) x axis (0, 0, 1)
  circle C1 centre (192.5, 285.4208) radius 4
  circle C2 centre (192.5, 315.4208) radius 4
hole "Hole1" HoleDiameter 4 TipAngle 180 CBDepth 13.4 CBDiameter 8
mirror "Mirror2" mirrorStitchTolerance 0.1
sketch "Sketch14" plane through (0, 327.4208, 0) normal (0, 1, 0) x axis (-1, 0, 0)
  line L1 (-31.6668, 173.4615) -> (-43.4822, 172.9384)
  line L2 (37.2412, 176.2252) -> (39.6909, 169.5703)
  line L3 (-21.0401, 223.4114) -> (18.2508, 223.4114)
  line L4 (-11.3947, 189.3) -> (-11.3947, 183.5)
  line L5 (-9.5947, 189.3) -> (-11.3947, 189.3)
  line L6 (-9.5947, 187.55) -> (-9.5947, 189.3)
  line L7 (-8.0018, 187.05) -> (-9.0947, 187.05)
  line L8 (-5.4411, 189.4036) -> (-7.6482, 187.1964)
  line L9 (-5.2947, 195.2429) -> (-5.2947, 189.7571)
  line L10 (-7.6482, 197.8036) -> (-5.4411, 195.5964)
  line L11 (-9.0947, 197.95) -> (-8.0018, 197.95)
  line L12 (-9.5947, 195.7) -> (-9.5947, 197.45)
  line L13 (-11.3947, 195.7) -> (-9.5947, 195.7)
  line L14 (-11.3947, 201.5) -> (-11.3947, 195.7)
  line L15 (-4.5947, 202.5) -> (-10.3947, 202.5)
  line L16 (-4.5947, 200.7) -> (-4.5947, 202.5)
  line L17 (-6.3447, 200.7) -> (-4.5947, 200.7)
  line L18 (-6.8447, 199.1071) -> (-6.8447, 200.2)
  line L19 (-4.4911, 196.5464) -> (-6.6982, 198.7536)
  line L20 (1.3482, 196.4) -> (-4.1375, 196.4)
  line L21 (3.9089, 198.7536) -> (1.7018, 196.5464)
  line L22 (4.0553, 200.2) -> (4.0553, 199.1071)
  line L23 (1.8053, 200.7) -> (3.5553, 200.7)
  line L24 (1.8053, 202.5) -> (1.8053, 200.7)
  line L25 (7.6053, 202.5) -> (1.8053, 202.5)
  line L26 (8.6053, 195.7) -> (8.6053, 201.5)
  line L27 (6.8053, 195.7) -> (8.6053, 195.7)
  line L28 (6.8053, 197.45) -> (6.8053, 195.7)
  line L29 (5.2125, 197.95) -> (6.3053, 197.95)
  line L30 (2.6518, 195.5964) -> (4.8589, 197.8036)
  line L31 (2.5053, 189.7571) -> (2.5053, 195.2429)
  line L32 (4.8589, 187.1964) -> (2.6518, 189.4036)
  line L33 (6.3053, 187.05) -> (5.2125, 187.05)
  line L34 (6.8053, 189.3) -> (6.8053, 187.55)
  line L35 (8.6053, 189.3) -> (6.8053, 189.3)
  line L36 (8.6053, 183.5) -> (8.6053, 189.3)
  line L37 (1.8053, 182.5) -> (7.6053, 182.5)
  line L38 (1.8053, 184.3) -> (1.8053, 182.5)
  line L39 (3.5553, 184.3) -> (1.8053, 184.3)
  line L40 (4.0553, 185.8929) -> (4.0553, 184.8)
  line L41 (1.7018, 188.4536) -> (3.9089, 186.2464)
  line L42 (-4.1375, 188.6) -> (1.3482, 188.6)
  line L43 (-6.6982, 186.2464) -> (-4.4911, 188.4536)
  line L44 (-6.8447, 184.8) -> (-6.8447, 185.8929)
  line L45 (-4.5947, 184.3) -> (-6.3447, 184.3)
  line L46 (-4.5947, 182.5) -> (-4.5947, 184.3)
  line L47 (-10.3947, 182.5) -> (-4.5947, 182.5)
  line L48 (3.6968, 198.9657) -> (1.4897, 196.7586)
  line L49 (3.7553, 200.2) -> (3.7553, 199.1071)
  line L50 (1.5053, 200.4) -> (3.5553, 200.4)
  line L51 (1.5053, 202.8) -> (1.5053, 200.4)
  line L52 (7.6053, 202.8) -> (1.5053, 202.8)
  line L53 (8.9053, 195.4) -> (8.9053, 201.5)
  line L54 (6.5053, 195.4) -> (8.9053, 195.4)
  line L55 (6.5053, 197.45) -> (6.5053, 195.4)
  line L56 (5.2125, 197.65) -> (6.3053, 197.65)
  line L57 (2.8639, 195.3843) -> (5.071, 197.5914)
  line L58 (2.8053, 189.7571) -> (2.8053, 195.2429)
  line L59 (5.071, 187.4086) -> (2.8639, 189.6157)
  line L60 (6.3053, 187.35) -> (5.2125, 187.35)
  line L61 (6.5053, 189.6) -> (6.5053, 187.55)
  line L62 (8.9053, 189.6) -> (6.5053, 189.6)
  line L63 (8.9053, 183.5) -> (8.9053, 189.6)
  line L64 (1.5053, 182.2) -> (7.6053, 182.2)
  line L65 (1.5053, 184.6) -> (1.5053, 182.2)
  line L66 (3.5553, 184.6) -> (1.5053, 184.6)
  line L67 (3.7553, 185.8929) -> (3.7553, 184.8)
  line L68 (1.4897, 188.2414) -> (3.6968, 186.0343)
  line L69 (-4.1375, 188.3) -> (1.3482, 188.3)
  line L70 (-6.4861, 186.0343) -> (-4.279, 188.2414)
  line L71 (-6.5447, 184.8) -> (-6.5447, 185.8929)
  line L72 (-4.2947, 184.6) -> (-6.3447, 184.6)
  line L73 (-4.2947, 182.2) -> (-4.2947, 184.6)
  line L74 (-10.3947, 182.2) -> (-4.2947, 182.2)
  line L75 (-11.6947, 189.6) -> (-11.6947, 183.5)
  line L76 (-9.2947, 189.6) -> (-11.6947, 189.6)
  line L77 (-9.2947, 187.55) -> (-9.2947, 189.6)
  line L78 (-8.0018, 187.35) -> (-9.0947, 187.35)
  line L79 (-5.6532, 189.6157) -> (-7.8603, 187.4086)
  line L80 (-5.5947, 195.2429) -> (-5.5947, 189.7571)
  line L81 (-7.8603, 197.5914) -> (-5.6532, 195.3843)
  line L82 (-9.0947, 197.65) -> (-8.0018, 197.65)
  line L83 (-9.2947, 195.4) -> (-9.2947, 197.45)
  line L84 (-11.6947, 195.4) -> (-9.2947, 195.4)
  line L85 (-11.6947, 201.5) -> (-11.6947, 195.4)
  line L86 (-4.2947, 202.8) -> (-10.3947, 202.8)
  line L87 (-4.2947, 200.4) -> (-4.2947, 202.8)
  line L88 (-6.3447, 200.4) -> (-4.2947, 200.4)
  line L89 (-6.5447, 199.1071) -> (-6.5447, 200.2)
  line L90 (-4.279, 196.7586) -> (-6.4861, 198.9657)
  line L91 (1.3482, 196.7) -> (-4.1375, 196.7)
  line L92 (-11.6947, 195.4) -> (-11.6947, 189.6)
  line L93 (8.9053, 195.4) -> (8.9053, 189.6)
  line L94 (-5.4447, 200.7) -> (-5.4447, 184.3)
  line L95 (2.6553, 200.7) -> (2.6553, 184.3)
  arc A1 centre (0, 97.9412) radius 86.6908 clockwise from (37.2412, 176.2252) to (-43.4822, 172.9384)
  arc A2 centre (0, 97.9412) radius 81.8908 clockwise from (39.6909, 169.5703) to (-31.6668, 173.4615)
  arc A3 centre (0, 97.9412) radius 92.5 clockwise from (56.4687, 171.2046) to (-58.7024, 169.4274)
  arc A4 centre (211.2843, 324.6293) radius 217.961 clockwise from (56.4687, 171.2046) to (18.2508, 223.4114)
  arc A5 centre (-216.5788, 319.7006) radius 217.961 clockwise from (-21.0401, 223.4114) to (-58.7024, 169.4274)
  circle C1 centre (0, 97.9412) radius 74.7
  arc A6 centre (-10.3947, 183.5) radius 1 clockwise from (-10.3947, 182.5) to (-11.3947, 183.5)
  arc A7 centre (-9.0947, 187.55) radius 0.5 clockwise from (-9.0947, 187.05) to (-9.5947, 187.55)
  arc A8 centre (-8.0018, 187.55) radius 0.5 clockwise from (-7.6482, 187.1964) to (-8.0018, 187.05)
  arc A9 centre (-5.7947, 189.7571) radius 0.5 clockwise from (-5.2947, 189.7571) to (-5.4411, 189.4036)
  arc A10 centre (-5.7947, 195.2429) radius 0.5 clockwise from (-5.4411, 195.5964) to (-5.2947, 195.2429)
  arc A11 centre (-8.0018, 197.45) radius 0.5 clockwise from (-8.0018, 197.95) to (-7.6482, 197.8036)
  arc A12 centre (-9.0947, 197.45) radius 0.5 clockwise from (-9.5947, 197.45) to (-9.0947, 197.95)
  arc A13 centre (-10.3947, 201.5) radius 1 clockwise from (-11.3947, 201.5) to (-10.3947, 202.5)
  arc A14 centre (-6.3447, 200.2) radius 0.5 clockwise from (-6.8447, 200.2) to (-6.3447, 200.7)
  arc A15 centre (-6.3447, 199.1071) radius 0.5 clockwise from (-6.6982, 198.7536) to (-6.8447, 199.1071)
  arc A16 centre (-4.1375, 196.9) radius 0.5 clockwise from (-4.1375, 196.4) to (-4.4911, 196.5464)
  arc A17 centre (1.3482, 196.9) radius 0.5 clockwise from (1.7018, 196.5464) to (1.3482, 196.4)
  arc A18 centre (3.5553, 199.1071) radius 0.5 clockwise from (4.0553, 199.1071) to (3.9089, 198.7536)
  arc A19 centre (3.5553, 200.2) radius 0.5 clockwise from (3.5553, 200.7) to (4.0553, 200.2)
  arc A20 centre (7.6053, 201.5) radius 1 clockwise from (7.6053, 202.5) to (8.6053, 201.5)
  arc A21 centre (6.3053, 197.45) radius 0.5 clockwise from (6.3053, 197.95) to (6.8053, 197.45)
  arc A22 centre (5.2125, 197.45) radius 0.5 clockwise from (4.8589, 197.8036) to (5.2125, 197.95)
  arc A23 centre (3.0053, 195.2429) radius 0.5 clockwise from (2.5053, 195.2429) to (2.6518, 195.5964)
  arc A24 centre (3.0053, 189.7571) radius 0.5 clockwise from (2.6518, 189.4036) to (2.5053, 189.7571)
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  point P213 (-5.4447, 184.3)
  point P214 (-5.4447, 200.7)
  point P215 (2.6553, 184.3)
  point P216 (2.6553, 200.7)
  coincident L45 P213
  coincident L17 P214
  vertical L94
  coincident L39 P215
  coincident L23 P216
  perpendicular L23 L95
  dimension "d100" = -0.3
  dimension "d103" distance L18 L94 = 1.4
  dimension "d104" distance L22 L95 = 1.4
extrude "Extrude14" cut sketch "Sketch14" against normal blind 57.53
